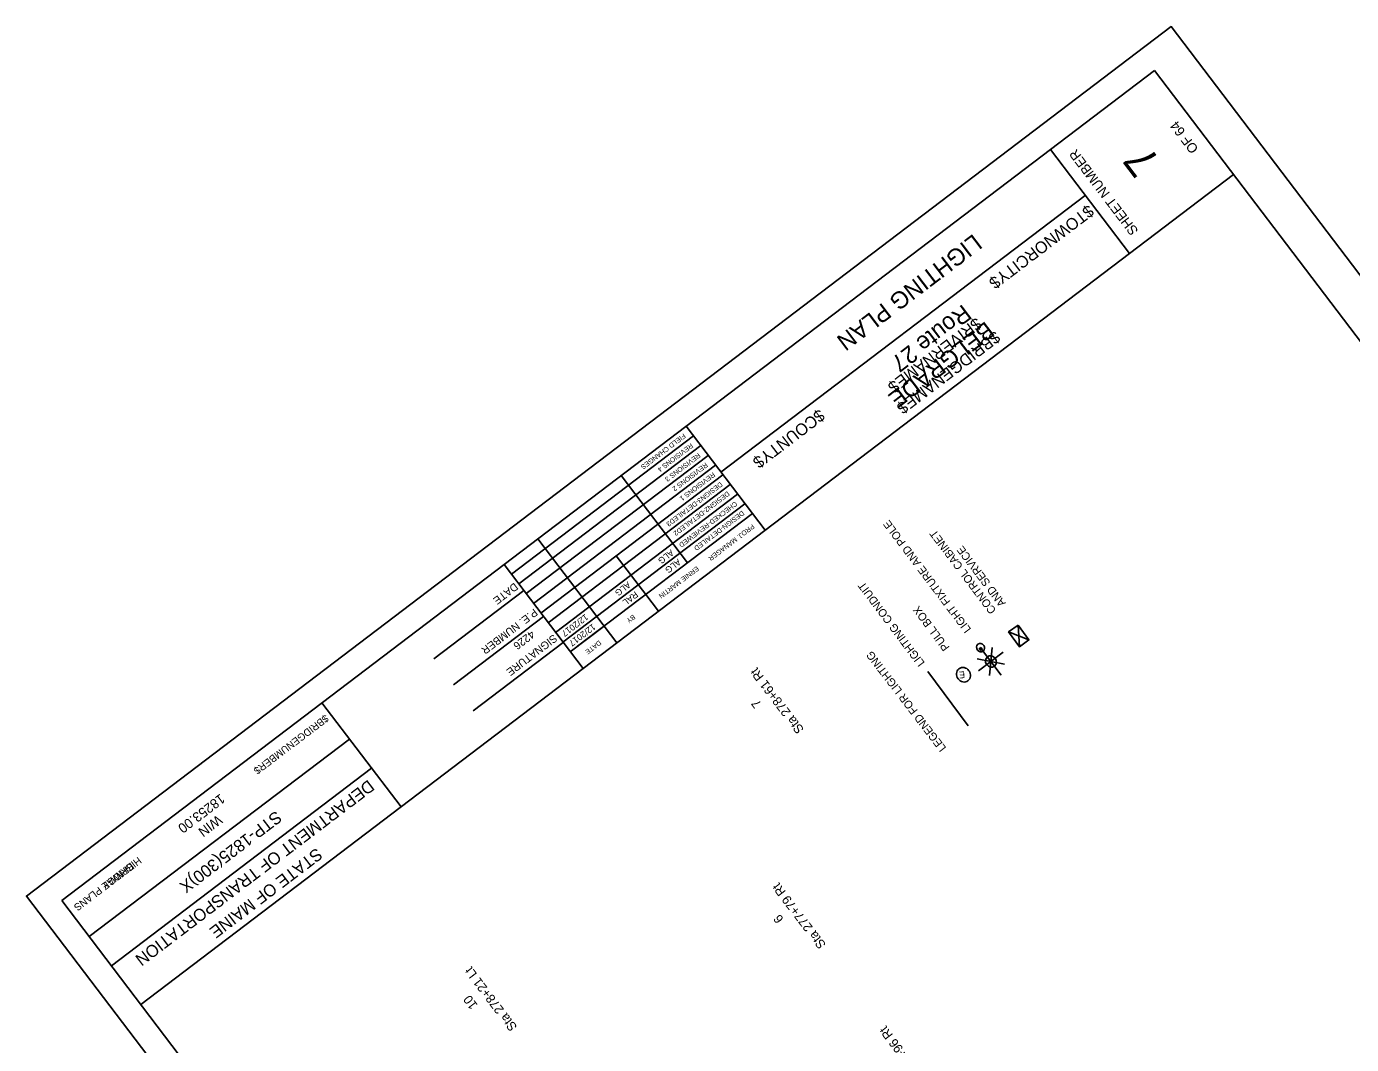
# Model space of a CAD drawing. Extents: x 1111477 to 1112429, y 616480 to 617490.
# Drawn here: x 1111477 to 1111984, y 617100 to 617490 of the extents above; entities that cross this region are included whole.
import ezdxf

# ---------------------------------------------------------------- set-up
doc = ezdxf.new("R2010")
doc.units = 0
for name, color, linetype in [('ANNOTATION', 7, 'Continuous'), ('BRIDGE_TITLE', 7, 'Continuous'), ('D_Lighting', 7, 'Continuous'), ('D_LIGHTING_ANNOTATION', 7, 'Continuous'), ('HIGHWAY_TITLE', 7, 'Continuous'), ('Liting Text', 7, 'Continuous'), ('Prp Liting', 7, 'Continuous'), ('UTILS GRND', 7, 'Continuous'), ('VSL-LUMINAIRES', 7, 'Continuous'), ('VSL-LUMINAIRESCHEDULES', 7, 'Continuous'), ('VSL-STATISTICS', 7, 'Continuous')]:
    doc.layers.add(name, color=color, linetype=linetype)

msp = doc.modelspace()

# ---------------------------------------------------------------- linework, layer by layer
msp.add_lwpolyline([(1111990.86, 616480.3), (1111476.68, 617157.15), (1111914.64, 617489.85), (1112428.82, 616813)], close=True)
at = {"layer": 'D_Lighting'}
for p, q in [((1111856.07, 617260.82), (1111856.62, 617252.48)), ((1111860.22, 617255.11), (1111852.46, 617258.19)), ((1111841.71, 617252.16), (1111845.67, 617246.89)), ((1111845.67, 617246.89), (1111846.14, 617252.22)), ((1111845.67, 617246.89), (1111840.42, 617247.92)), ((1111845.67, 617246.89), (1111840.92, 617243.32)), ((1111845.67, 617246.89), (1111845.19, 617241.56)), ((1111845.67, 617246.89), (1111850.41, 617250.45)), ((1111845.67, 617246.89), (1111849.62, 617241.62)), ((1111845.67, 617246.89), (1111850.91, 617245.86))]:
    msp.add_line(p, q, dxfattribs=at)
msp.add_lwpolyline([(1111856.07, 617260.82), (1111860.22, 617255.11), (1111856.62, 617252.48), (1111852.46, 617258.19)], close=True, dxfattribs=at)
for centre, major_axis in [((1111841.71, 617252.16), (-0.99, 1.32)), ((1111845.67, 617246.89), (-1.35, 1.8))]:
    msp.add_ellipse(centre, major_axis=major_axis, ratio=0.899857, dxfattribs=at)
at = {"layer": 'Prp Liting'}
msp.add_line((1111836.94, 617222.29), (1111821.58, 617243.01), dxfattribs=at)
at = {"layer": 'UTILS GRND'}
msp.add_ellipse((1111835.17, 617241.81), major_axis=(1.73, -2.3), ratio=0.901044, dxfattribs=at)
at = {"layer": 'VSL-LUMINAIRES'}
msp.add_lwpolyline([(1111841.79, 617252.22), (1111841.23, 617251.77), (1111841.71, 617251.18), (1111842.28, 617251.63)], close=True, dxfattribs=at)
msp.add_lwpolyline([(1111841.79, 617252.22), (1111841.23, 617251.77), (1111841.71, 617251.18), (1111842.28, 617251.63)], close=True, dxfattribs=at)
msp.add_lwpolyline([(1111841.71, 617252.16), (1111841.71, 617252.16)], dxfattribs=at)
at = {"layer": 'VSL-LUMINAIRESCHEDULES'}
msp.add_lwpolyline([(1112428.82, 616813), (1111914.64, 617489.85), (1111476.68, 617157.15), (1111990.86, 616480.3)], close=True, dxfattribs=at)
at = {"layer": 'VSL-STATISTICS'}
for p, q in [((1111908.22, 617473), (1111490.17, 617155.42)), ((1112392.16, 616835.98), (1111908.23, 617473.01)), ((1111898.65, 617402.94), (1111868.41, 617442.75)), ((1111938.47, 617433.18), (1111520.41, 617115.61)), ((1111881.74, 617425.2), (1111742.39, 617319.34)), ((1111759.3, 617297.08), (1111729.05, 617336.89)), ((1111689.62, 617244.15), (1111659.38, 617283.96)), ((1111666.94, 617274.01), (1111632.51, 617247.86)), ((1111674.5, 617264.06), (1111640.07, 617237.9)), ((1111682.06, 617254.1), (1111647.63, 617227.95)), ((1111619.98, 617191.25), (1111589.74, 617231.06)), ((1111600.24, 617217.21), (1111500.71, 617141.6)), ((1111608.7, 617206.08), (1111509.16, 617130.47)), ((1111490.18, 617155.43), (1111974.11, 616518.4))]:
    msp.add_line(p, q, dxfattribs=at)
for points in [[(1111731.86, 617333.18), (1111662.19, 617280.26)], [(1111734.68, 617329.47), (1111665.01, 617276.55)], [(1111737.49, 617325.76), (1111667.83, 617272.84)], [(1111740.31, 617322.05), (1111670.65, 617269.13)], [(1111743.13, 617318.34), (1111673.47, 617265.42)], [(1111729.53, 617284.6), (1111704.17, 617317.99)], [(1111745.95, 617314.63), (1111676.28, 617261.71)], [(1111679.1, 617258), (1111748.77, 617310.92)], [(1111751.58, 617307.21), (1111681.92, 617254.29)], [(1111754.4, 617303.5), (1111687.55, 617252.72)], [(1111702.56, 617253.98), (1111672.32, 617293.79)], [(1111713.61, 617272.51), (1111702.33, 617287.34)], [(1111718.49, 617266.08), (1111713.6, 617272.51)], [(1111697.68, 617260.41), (1111684.74, 617250.58)]]:
    msp.add_lwpolyline(points, dxfattribs=at)

# ---------------------------------------------------------------- texts
at = {"layer": 'ANNOTATION'}
msp.add_text('4226', height=3, rotation=217.2225, dxfattribs=at).set_placement((1111669.75, 617258.95))
at = {"layer": 'BRIDGE_TITLE'}
for s, height, p in [('$TOWNORCITY$', 4.5358, (1111882.89, 617421.86)), ('$RIVERNAME$', 4.5358, (1111839.94, 617378.7)), ('$BRIDGENAME$', 4.5358, (1111847.06, 617373.58)), ('$COUNTY$', 4.536, (1111779.94, 617343.65)), ('$BRIDGENUMBER$', 2.795, (1111590.95, 617226.69)), ('BRIDGE PLANS', 2.795, (1111516.52, 617170.15))]:
    msp.add_text(s, height=height, rotation=217.2225, dxfattribs=at).set_placement(p)
at = {"layer": 'D_LIGHTING_ANNOTATION'}
for s, p in [('Sta 278+61 Rt', (1111774.31, 617220.91)), ('7', (1111758.08, 617230.7)), ('Sta 277+79 Rt', (1111782.74, 617138.59)), ('6', (1111766.53, 617148.36)), ('Sta 278+21 Lt', (1111664.6, 617107.09)), ('10', (1111649.48, 617115.42)), ('Sta 276+96 Rt', (1111823.7, 617083.78))]:
    msp.add_text(s, height=3.5, rotation=127.2225, dxfattribs=at).set_placement(p)
at = {"layer": 'HIGHWAY_TITLE'}
for s, height, p in [('Route 27', 6.521, (1111834.96, 617383.81)), ('BELGRADE', 6.521, (1111843.67, 617377.32)), ('HIGHWAY PLANS', 2.795, (1111519.34, 617172.3))]:
    msp.add_text(s, height=height, rotation=217.2225, dxfattribs=at).set_placement(p)
at = {"layer": 'Liting Text'}
for s, height, rotation, p in [('LIGHT FIXTURE AND POLE', 3.0627, 126.8976, (1111838.25, 617259.23)), ('CONTROL CABINET ', 3.0627, 126.9762, (1111847.84, 617266.49)), ('AND SERVICE', 3.0627, 126.9762, (1111851.51, 617269.25)), ('LIGHTING CONDUIT', 3.0627, 126.8976, (1111820.51, 617246.38)), ('PULL BOX', 3.063, 126.5451, (1111830.02, 617252.31)), ('LEGEND FOR LIGHTING', 3.0627, 127.4298, (1111828.74, 617213.81))]:
    msp.add_text(s, height=height, rotation=rotation, dxfattribs=at).set_placement(p)
at = {"layer": 'UTILS GRND'}
msp.add_text('E', height=2.58, rotation=184.186, dxfattribs=at).set_placement((1111835.66, 617243.14))
at = {"layer": 'VSL-STATISTICS'}
for s, height, rotation, p in [('OF 64', 3.726, 127.2225, (1111925.26, 617443.04)), ('SHEET NUMBER', 3.7264, 127.2225, (1111902.25, 617411.73)), ('7', 12.1, 127.2225, (1111910.75, 617438.42)), ('LIGHTING PLAN', 6.5214, 217.2225, (1111838.99, 617410.77)), ('FIELD CHANGES', 1.8637, 217.2225, (1111728.01, 617334.23)), ('REVISIONS 4', 1.8637, 217.2225, (1111730.83, 617330.52)), ('REVISIONS 3', 1.8637, 217.2225, (1111733.65, 617326.81)), ('REVISIONS 2', 1.8637, 217.2225, (1111736.46, 617323.11)), ('REVISIONS 1', 1.8637, 217.2225, (1111739.28, 617319.4)), ('DESIGN3-DETAILED3', 1.8637, 217.2225, (1111742.1, 617315.69)), ('DESIGN2-DETAILED2', 1.8637, 217.2225, (1111744.81, 617312.13)), ('CHECKED-REVIEWED', 1.8637, 217.2225, (1111747.74, 617308.27)), ('DESIGN-DETAILED', 1.8637, 217.2225, (1111750.44, 617304.71)), ('PROJ. MANAGER', 1.8637, 217.2225, (1111754.32, 617299.6)), ('ALG', 2.423, 217.2225, (1111723.2, 617289.86)), ('ALG', 2.423, 217.2225, (1111725.9, 617286.3)), ('ERNIE MARTIN', 1.8637, 217.2225, (1111733.09, 617283.47)), ('DATE', 2.953, 217.2225, (1111663.33, 617277.18)), ('ALG', 2.423, 217.2225, (1111706.71, 617277.57)), ('RAL', 2.423, 217.2225, (1111709.53, 617273.86)), ('P.E. NUMBER', 2.9528, 217.2225, (1111670.83, 617267.3)), ('12/2017', 2.423, 217.2225, (1111690.46, 617265.22)), ('12/2017', 2.423, 217.2225, (1111693.28, 617261.51)), ('BY', 1.857, 217.2225, (1111708.74, 617264.98)), ('SIGNATURE', 2.953, 217.2225, (1111678.33, 617257.43)), ('DATE', 1.857, 217.2225, (1111695.72, 617255.09)), ('DEPARTMENT OF TRANSPORTATION', 4.6588, 217.2225, (1111607.45, 617201.86)), ('18253.00', 3.726, 217.2225, (1111550.82, 617196.45)), ('STP-1825(300)X', 4.6588, 217.2225, (1111572.1, 617189.99)), ('WIN', 3.726, 217.2225, (1111549.75, 617188.35)), ('STATE OF MAINE', 4.6588, 217.2225, (1111587.64, 617175.81))]:
    msp.add_text(s, height=height, rotation=rotation, dxfattribs=at).set_placement(p)

doc.saveas('drawing.dxf')
